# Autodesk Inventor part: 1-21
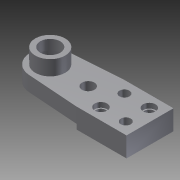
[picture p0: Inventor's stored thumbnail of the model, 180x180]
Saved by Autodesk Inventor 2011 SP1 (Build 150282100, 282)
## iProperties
Created: 2014-02
Part Number: 1-21
Document SubType Name: Modeling
Designer: Administrator
Density: 1 g/cm^3
Author: Administrator
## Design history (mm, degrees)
sketch "草图1"
  geometry: L1 (0, 9.45)-(20, 9.45); L2 (20, 9.45)-(20, -9.45); L3 (20, -9.45)-(0, -9.45); L4 (0, 9.45)-(-20.685, 7.98); L5 (0, -9.45)-(-20.685, -7.98); A1 r 8 centre (-20.119, 0) between (-20.685, 7.98) and (-20.685, -7.98); 2 further points
  constraints: 10 end point, 2 point on circle, 2 tangent, 1 centre point, 1 coincident, 1 horizontal, 1 parallel, 1 perpendicular
  dimensions: "d0" = 16 diameter of A1
extrude "拉伸1" new body sketch "草图1" distance "d1" = 6; taper "d2" = 0 deg
sketch "草图2"
  geometry: C1 r 6 at (-20.119, 0); A1 r 8 centre (-20.119, 0) between (-20.685, 7.98) and (-20.685, -7.98) reference; 1 further point
  constraints: 1 centre point, 1 coincident
  dimensions: "d3" = 12 diameter of C1
extrude "拉伸2" join sketch "草图2" distance "d4" = 6; taper "d5" = 0 deg
sketch "草图3"
  geometry: C1 r 6 at (0, 0) reference; C2 r 4 at (0, 0); 1 further point
  constraints: 1 centre point, 1 coincident
  dimensions: "d6" = 8 diameter of C2
extrude "拉伸3" cut sketch "草图3" stored distance "d7" = 6; taper "d8" = 0 deg
sketch "草图4"
  geometry: C1 r 4 at (20.119, 0) reference; C2 r 5 at (20.119, 0); A1 r 8 centre (20.119, 0) between (20.685, -7.98) and (20.685, 7.98) reference; 1 further point
  constraints: 1 centre point, 1 coincident
  dimensions: "d9" = 10 diameter of C2
extrude "拉伸4" cut sketch "草图4" distance "d10" = 8; taper "d11" = 0 deg
sketch "草图5"
  geometry: C1 r 2.5 at (-4.839, 0); 1 further point
  constraints: 1 centre point
  dimensions: "d12" = 5 diameter of C1
extrude "拉伸5" cut sketch "草图5" stored distance "d13" = 8; taper "d14" = 0 deg
sketch "草图6"
  geometry: L1 (0, 9.45)-(-20, 9.45) reference; L2 (-20, 9.45)-(-20, -9.45) reference; L3 (-20, -9.45)-(0, -9.45); L4 (0, -9.45)-(0, 9.45); L5 (0, 9.45)-(-20, 9.45); L6 (-20, 9.45)-(-20, -9.45); 1 further point
  constraints: 8 end point, 2 parallel, 1 horizontal, 1 perpendicular
extrude "拉伸6" join sketch "草图6" distance "d15" = 2; taper "d16" = 0 deg
sketch "草图7"
  geometry: C1 r 2 at (5, 4.725); C2 r 2 at (5, -4.725); C3 r 2 at (15, -4.725); C4 r 2 at (15, 4.725); 1 further point
  constraints: 4 centre point
  dimensions: "d17" = 4 diameter of C1; "d18" = 4 diameter of C2; "d19" = 4 diameter of C3
extrude "拉伸7" cut sketch "草图7" stored distance "d20" = 2; taper "d21" = 0 deg
sketch "草图8"
  geometry: C1 r 2 at (5, -4.725) reference; C2 r 2 at (15, 4.725) reference; C3 r 2.5 at (5, -4.725); C4 r 2.5 at (15, 4.725); 1 further point
  constraints: 2 centre point, 2 coincident
  dimensions: "d22" = 5 diameter of C3; "d23" = 5 diameter of C4
extrude "拉伸8" cut sketch "草图8" distance "d24" = 2; taper "d25" = 0 deg
node "实体1"
